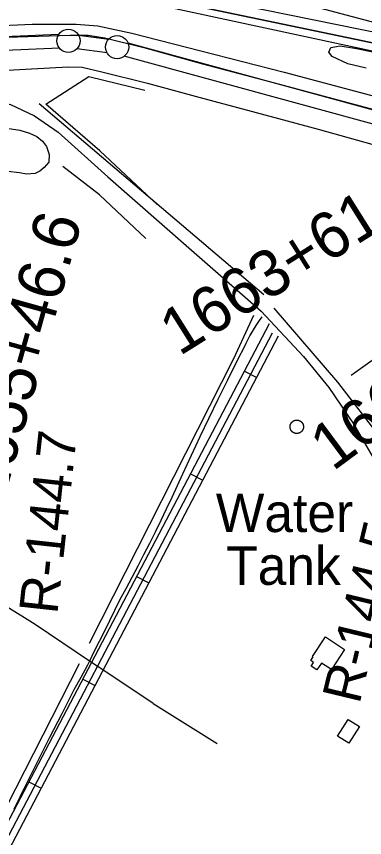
# Model space of a CAD drawing. Extents: x 3477039 to 3515015, y 546746 to 572297.
# Drawn here: x 3495798 to 3496548, y 561275 to 563045 of the extents above; entities that cross this region are included whole.
import ezdxf

# ---------------------------------------------------------------- set-up
doc = ezdxf.new("R2010")
doc.units = 0
for name, color, linetype in [('V-BLDG-OTLN', 7, 'Continuous'), ('V-DOMW-IDEN', 7, 'Continuous'), ('V-DOMW-TANK', 7, 'Continuous'), ('V-DTCH-CNTR', 7, 'Continuous'), ('V-FLOD-BASE', 7, 'Continuous'), ('V-LEVE-TOET', 7, 'Continuous'), ('V-RIVR-RANG-IDEN', 7, 'Continuous'), ('V-ROAD-CNTR', 7, 'Continuous'), ('V-RRAP-FSHR', 7, 'Continuous'), ('V-SITE-VEGE', 7, 'Continuous'), ('V-SURV-IDEN', 7, 'Continuous'), ('V-SURV-LINE', 7, 'Continuous'), ('V-TOPO-DPTH', 7, 'Continuous'), ('V-TOPO-MINR', 7, 'Continuous'), ('V-TOPO-SHOR', 7, 'Continuous')]:
    doc.layers.add(name, color=color, linetype=linetype)

msp = doc.modelspace()

# ---------------------------------------------------------------- linework, layer by layer
at = {"layer": 'V-BLDG-OTLN'}
for points in [[(3496463.4, 561707.2), (3496504.8, 561680.2), (3496476.7, 561637), (3496454.9, 561651.1), (3496445.3, 561636.4), (3496433, 561644.3), (3496438.2, 561652.3), (3496432.2, 561656.3), (3496437.3, 561664.2), (3496435.4, 561665.4)], [(3496512.8, 561529.5), (3496536.9, 561514.1), (3496513.9, 561478.2), (3496489.6, 561493.7)]]:
    msp.add_lwpolyline(points, close=True, dxfattribs=at)
at = {"layer": 'V-DOMW-TANK'}
for points in [[(3496387.7, 562163.5), (3496387.7, 562163.8), (3496387.8, 562164), (3496387.9, 562164.3), (3496387.9, 562164.5), (3496388, 562164.7), (3496388.1, 562165), (3496388.2, 562165.2), (3496388.2, 562165.5), (3496388.3, 562165.7), (3496388.4, 562165.9), (3496388.5, 562166.2), (3496388.6, 562166.4), (3496388.7, 562166.6), (3496388.8, 562166.9), (3496388.9, 562167.1), (3496389.1, 562167.3), (3496389.2, 562167.5), (3496389.3, 562167.7), (3496389.4, 562168), (3496389.6, 562168.2), (3496389.7, 562168.4), (3496389.8, 562168.6), (3496390, 562168.8), (3496390.1, 562169), (3496390.3, 562169.2), (3496390.4, 562169.4), (3496390.6, 562169.6), (3496390.8, 562169.8), (3496390.9, 562170), (3496391.1, 562170.2), (3496391.3, 562170.4), (3496391.4, 562170.6), (3496391.6, 562170.7), (3496391.8, 562170.9), (3496392, 562171.1), (3496392.2, 562171.3), (3496392.4, 562171.4), (3496392.6, 562171.6), (3496392.7, 562171.7), (3496392.9, 562171.9), (3496393.1, 562172.1), (3496393.3, 562172.2), (3496393.6, 562172.4), (3496393.8, 562172.5), (3496394, 562172.6), (3496394.2, 562172.8), (3496394.4, 562172.9), (3496394.6, 562173), (3496394.8, 562173.2), (3496395.1, 562173.3), (3496395.3, 562173.4), (3496395.5, 562173.5), (3496395.7, 562173.6), (3496396, 562173.7), (3496396.2, 562173.8), (3496396.4, 562173.9), (3496396.7, 562174), (3496396.9, 562174.1), (3496397.1, 562174.2), (3496397.4, 562174.3)], [(3496397.4, 562174.3), (3496397.6, 562174.3), (3496397.9, 562174.4), (3496398.1, 562174.5), (3496398.4, 562174.5), (3496398.6, 562174.6), (3496398.9, 562174.6), (3496399.1, 562174.7), (3496399.3, 562174.7), (3496399.6, 562174.8), (3496399.8, 562174.8), (3496400.1, 562174.8), (3496400.3, 562174.9), (3496400.6, 562174.9), (3496400.9, 562174.9), (3496401.1, 562174.9), (3496401.4, 562174.9), (3496401.6, 562174.9), (3496401.9, 562175), (3496402.1, 562174.9), (3496402.4, 562174.9), (3496402.6, 562174.9), (3496402.9, 562174.9), (3496403.1, 562174.9), (3496403.4, 562174.9), (3496403.6, 562174.8), (3496403.9, 562174.8), (3496404.1, 562174.8), (3496404.4, 562174.7), (3496404.6, 562174.7), (3496404.9, 562174.6), (3496405.1, 562174.6), (3496405.4, 562174.5), (3496405.6, 562174.4), (3496405.8, 562174.4), (3496406.1, 562174.3), (3496406.3, 562174.2), (3496406.6, 562174.2), (3496406.8, 562174.1), (3496407, 562174), (3496407.3, 562173.9), (3496407.5, 562173.8), (3496407.7, 562173.7), (3496408, 562173.6), (3496408.2, 562173.5), (3496408.4, 562173.4), (3496408.7, 562173.2), (3496408.9, 562173.1), (3496409.1, 562173), (3496409.3, 562172.9), (3496409.5, 562172.7), (3496409.7, 562172.6), (3496409.9, 562172.5), (3496410.2, 562172.3), (3496410.4, 562172.2), (3496410.6, 562172), (3496410.8, 562171.9), (3496411, 562171.7), (3496411.2, 562171.5), (3496411.3, 562171.4), (3496411.5, 562171.2), (3496411.7, 562171), (3496411.9, 562170.9), (3496412.1, 562170.7), (3496412.3, 562170.5), (3496412.4, 562170.3), (3496412.6, 562170.1), (3496412.8, 562169.9), (3496412.9, 562169.8), (3496413.1, 562169.6), (3496413.3, 562169.4), (3496413.4, 562169.2), (3496413.6, 562169), (3496413.7, 562168.7), (3496413.8, 562168.5), (3496414, 562168.3), (3496414.1, 562168.1), (3496414.2, 562167.9), (3496414.4, 562167.7), (3496414.5, 562167.5), (3496414.6, 562167.2), (3496414.7, 562167), (3496414.9, 562166.8), (3496415, 562166.6), (3496415.1, 562166.3), (3496415.2, 562166.1), (3496415.3, 562165.9), (3496415.4, 562165.6), (3496415.4, 562165.4), (3496415.5, 562165.2), (3496415.6, 562164.9), (3496415.7, 562164.7), (3496415.7, 562164.4), (3496415.8, 562164.2), (3496415.9, 562163.9), (3496415.9, 562163.7), (3496416, 562163.4), (3496416, 562163.2), (3496416.1, 562163), (3496416.1, 562162.7), (3496416.2, 562162.5)], [(3496401.3, 562146), (3496401, 562146), (3496400.8, 562146), (3496400.5, 562146.1), (3496400.3, 562146.1), (3496400, 562146.1), (3496399.8, 562146.1), (3496399.5, 562146.2), (3496399.3, 562146.2), (3496399, 562146.3), (3496398.8, 562146.3), (3496398.5, 562146.4), (3496398.3, 562146.4), (3496398, 562146.5), (3496397.8, 562146.6), (3496397.6, 562146.6), (3496397.3, 562146.7), (3496397.1, 562146.8), (3496396.8, 562146.9), (3496396.6, 562147), (3496396.4, 562147.1), (3496396.1, 562147.2), (3496395.9, 562147.3), (3496395.7, 562147.4), (3496395.4, 562147.5), (3496395.2, 562147.6), (3496395, 562147.7), (3496394.8, 562147.8), (3496394.6, 562148), (3496394.3, 562148.1), (3496394.1, 562148.2), (3496393.9, 562148.4), (3496393.7, 562148.5), (3496393.5, 562148.6), (3496393.3, 562148.8), (3496393.1, 562148.9), (3496392.9, 562149.1), (3496392.7, 562149.3), (3496392.5, 562149.4), (3496392.3, 562149.6), (3496392.1, 562149.7), (3496391.9, 562149.9), (3496391.7, 562150.1), (3496391.6, 562150.3), (3496391.4, 562150.5), (3496391.2, 562150.6), (3496391, 562150.8), (3496390.9, 562151), (3496390.7, 562151.2), (3496390.6, 562151.4), (3496390.4, 562151.6), (3496390.2, 562151.8), (3496390.1, 562152), (3496389.9, 562152.2), (3496389.8, 562152.4), (3496389.7, 562152.6), (3496389.5, 562152.8), (3496389.4, 562153.1), (3496389.3, 562153.3), (3496389.1, 562153.5), (3496389, 562153.7), (3496388.9, 562153.9), (3496388.8, 562154.2), (3496388.7, 562154.4), (3496388.6, 562154.6), (3496388.5, 562154.9), (3496388.4, 562155.1), (3496388.3, 562155.3), (3496388.2, 562155.6), (3496388.1, 562155.8), (3496388, 562156), (3496388, 562156.3), (3496387.9, 562156.5), (3496387.8, 562156.8), (3496387.8, 562157), (3496387.7, 562157.3), (3496387.7, 562157.5), (3496387.6, 562157.8), (3496387.6, 562158), (3496387.5, 562158.2), (3496387.5, 562158.5), (3496387.5, 562158.8), (3496387.4, 562159), (3496387.4, 562159.3), (3496387.4, 562159.5), (3496387.4, 562159.8), (3496387.4, 562160), (3496387.4, 562160.3), (3496387.4, 562160.5), (3496387.4, 562160.8), (3496387.4, 562161), (3496387.4, 562161.3), (3496387.4, 562161.5), (3496387.4, 562161.8), (3496387.4, 562162), (3496387.5, 562162.3), (3496387.5, 562162.5), (3496387.5, 562162.8), (3496387.6, 562163), (3496387.6, 562163.3), (3496387.7, 562163.5)], [(3496416.2, 562162.5), (3496416.2, 562162.2), (3496416.2, 562162), (3496416.2, 562161.7), (3496416.3, 562161.4), (3496416.3, 562161.2), (3496416.3, 562160.9), (3496416.3, 562160.7), (3496416.3, 562160.4), (3496416.3, 562160.2), (3496416.3, 562159.9), (3496416.3, 562159.7), (3496416.3, 562159.4), (3496416.2, 562159.2), (3496416.2, 562158.9), (3496416.2, 562158.7), (3496416.2, 562158.4), (3496416.1, 562158.2), (3496416.1, 562157.9), (3496416, 562157.7), (3496416, 562157.4), (3496415.9, 562157.2), (3496415.9, 562156.9), (3496415.8, 562156.7), (3496415.7, 562156.5), (3496415.7, 562156.2), (3496415.6, 562156), (3496415.5, 562155.7), (3496415.4, 562155.5), (3496415.3, 562155.3), (3496415.2, 562155), (3496415.1, 562154.8), (3496415, 562154.6), (3496414.9, 562154.3), (3496414.8, 562154.1), (3496414.7, 562153.9), (3496414.6, 562153.6), (3496414.5, 562153.4), (3496414.3, 562153.2), (3496414.2, 562153), (3496414.1, 562152.8), (3496413.9, 562152.6), (3496413.8, 562152.4), (3496413.7, 562152.1), (3496413.5, 562151.9), (3496413.4, 562151.7), (3496413.2, 562151.5), (3496413, 562151.3), (3496412.9, 562151.1), (3496412.7, 562151), (3496412.6, 562150.8), (3496412.4, 562150.6), (3496412.2, 562150.4), (3496412, 562150.2), (3496411.9, 562150), (3496411.7, 562149.9), (3496411.5, 562149.7), (3496411.3, 562149.5), (3496411.1, 562149.4), (3496410.9, 562149.2), (3496410.7, 562149), (3496410.5, 562148.9), (3496410.3, 562148.7), (3496410.1, 562148.6), (3496409.9, 562148.5), (3496409.7, 562148.3), (3496409.5, 562148.2), (3496409.2, 562148.1), (3496409, 562147.9), (3496408.8, 562147.8), (3496408.6, 562147.7), (3496408.4, 562147.6), (3496408.1, 562147.5), (3496407.9, 562147.3), (3496407.7, 562147.2), (3496407.4, 562147.1), (3496407.2, 562147), (3496407, 562147), (3496406.7, 562146.9), (3496406.5, 562146.8), (3496406.3, 562146.7), (3496406, 562146.6), (3496405.8, 562146.6), (3496405.5, 562146.5), (3496405.3, 562146.4), (3496405, 562146.4), (3496404.8, 562146.3), (3496404.5, 562146.3), (3496404.3, 562146.2), (3496404.1, 562146.2), (3496403.8, 562146.1), (3496403.6, 562146.1), (3496403.3, 562146.1), (3496403, 562146.1), (3496402.8, 562146), (3496402.5, 562146), (3496402.3, 562146), (3496402, 562146), (3496401.8, 562146), (3496401.5, 562146), (3496401.3, 562146)]]:
    msp.add_lwpolyline(points, dxfattribs=at)
at = {"layer": 'V-DTCH-CNTR'}
msp.add_line((3496092.7, 561563.5), (3496230.4, 561477.2), dxfattribs=at)
for points in [[(3496100.8, 562640), (3495977.7, 562755.4), (3495860.9, 562856.2), (3495953.6, 562916), (3496074.4, 562886.3)], [(3496076.7, 562566.7), (3495977, 562660.9), (3495897.5, 562721.4)], [(3496291.7, 562339), (3496296.1, 562347.7), (3496300.7, 562356.3), (3496305.6, 562364.8), (3496310.7, 562373.1), (3496316, 562381.3), (3496321.4, 562389.4), (3496327.1, 562397.3)], [(3496291.7, 562339), (3496271.5, 562299.2), (3496251.6, 562259.3), (3496231.9, 562219.3), (3496212.4, 562179.2), (3496193.1, 562138.9), (3496174.1, 562098.6), (3496155.3, 562058.1), (3496143.9, 562033), (3496132.4, 562008), (3496120.6, 561983.1), (3496108.7, 561958.2), (3496096.6, 561933.4), (3496084.3, 561908.8), (3496071.8, 561884.2), (3496059.1, 561859.7), (3496046.3, 561835.3), (3496033.2, 561811.1), (3496020, 561786.9)], [(3496092.7, 561563.5), (3495988.2, 561633.5), (3495955.5, 561655.2), (3495838.1, 561734.1), (3495714.9, 561810.1), (3495577.1, 561906.2), (3495498.3, 561961.4), (3495426.5, 562008.9)], [(3496020, 561786.9), (3496009.3, 561764.3), (3495998.3, 561741.9), (3495987.2, 561719.5), (3495975.9, 561697.3), (3495964.4, 561675.1)], [(3495964.4, 561675.1), (3495955.5, 561655.2), (3495950.9, 561646.6), (3495936.4, 561619.8), (3495921.6, 561593.1), (3495895.3, 561541.7), (3495869.1, 561490.2), (3495843.2, 561438.6), (3495817.5, 561386.9), (3495792, 561335.1)]]:
    msp.add_lwpolyline(points, dxfattribs=at)
at = {"layer": 'V-FLOD-BASE'}
for points in [[(3493763, 562937.8), (3493748.8, 562924.4), (3493748.8, 562915), (3493805.7, 562921.6), (3493844.5, 562926), (3493958.3, 562926.9), (3494101.5, 562930.6), (3494248.8, 562935.3), (3494380.3, 562942.6), (3494565.2, 562950.6), (3494744.2, 562959.8), (3494932, 562967.2), (3495077, 562972.6), (3495230.8, 562980.2), (3495398.1, 562986.6), (3495569.5, 562993.5), (3495730.9, 562998.8), (3495913.4, 563005), (3495952.1, 563004.7), (3495987.9, 562999.2), (3496072.2, 562978)], [(3496072.2, 562978), (3496198.7, 562942.9), (3496343.4, 562904.8), (3496508.7, 562860.1), (3496656.3, 562821), (3496768.6, 562788.9), (3496803.4, 562777.9), (3496844.1, 562761), (3496913.6, 562725.7), (3496965.5, 562693.5), (3496995.8, 562668.8), (3497043.2, 562621.4), (3497108.2, 562557.2), (3497182.4, 562484.5), (3497238.1, 562426.8), (3497262.9, 562394.2), (3497296.6, 562345.4), (3497348.1, 562259.2), (3497396.8, 562175.9), (3497451.3, 562085.2), (3497489.7, 562020.6), (3497518.9, 561971.4), (3497528.3, 561980.6)]]:
    msp.add_lwpolyline(points, dxfattribs=at)
at = {"layer": 'V-LEVE-TOET'}
for points in [[(3495687.3, 563022.5), (3495831.7, 563028.6), (3495926.2, 563028.9), (3495973, 563024.7), (3496046.4, 563009.4), (3496195.3, 562971.3), (3496374.8, 562924.8), (3496582.3, 562869.7), (3496703.2, 562835.8), (3496803.2, 562802.4), (3496872.1, 562770.5), (3496948, 562726.3), (3497018.1, 562674.3), (3497080.3, 562617.5), (3497178.2, 562522), (3497242.1, 562455.1), (3497293.3, 562393.5), (3497347.4, 562301.4), (3497421.9, 562175.4), (3497485.6, 562065.2), (3497528.4, 561986.7)], [(3494322.5, 562867.4), (3494552.6, 562873.3), (3494731, 562882.5), (3494949.4, 562892.1), (3495113.2, 562902), (3495289.3, 562911.8), (3495465.3, 562916.9), (3495609.7, 562922.9), (3495764.7, 562928.8), (3495909.1, 562936.5), (3495939.3, 562935.6), (3495982, 562925.8)], [(3495982, 562925.8), (3496080.3, 562901.6), (3496182.9, 562873.4), (3496314.4, 562838.5), (3496447.6, 562802.3), (3496648.4, 562746.4), (3496704.3, 562730.4), (3496741.9, 562716.1), (3496840.5, 562671.8), (3496902.4, 562636), (3496942.9, 562607.8), (3496974.2, 562579.6), (3497053.4, 562503), (3497129.1, 562433), (3497160.8, 562404), (3497181.7, 562382.8), (3497213, 562349), (3497226.9, 562325.3), (3497280.1, 562233.5), (3497366.8, 562092.6), (3497411.8, 562018), (3497436.5, 561975), (3497448.6, 561954.8)]]:
    msp.add_lwpolyline(points, dxfattribs=at)
at = {"layer": 'V-ROAD-CNTR'}
for p, q in [((3496289, 562280.4), (3496315.6, 562266.5)), ((3496172.9, 562059), (3496199.4, 562045.1)), ((3496056.7, 561837.7), (3496083.3, 561823.7)), ((3495940.6, 561616.3), (3495967.1, 561602.3)), ((3495824.4, 561394.9), (3495851, 561381))]:
    msp.add_line(p, q, dxfattribs=at)
for points in [[(3494343.6, 562821.8), (3494659.2, 562837.7), (3494960.8, 562850.6), (3495266.7, 562866.1), (3495500.8, 562876.5), (3495620.7, 562881), (3495682.1, 562878.7), (3495733.3, 562869.5), (3495784.9, 562855.1), (3495836.7, 562830.8), (3495887.9, 562796.1), (3495994.9, 562699.2), (3496169.5, 562546.5), (3496324.8, 562410.1), (3496416.3, 562312.2), (3496470.9, 562245.2), (3496524.2, 562166.7), (3496592.4, 562048.9), (3496710.4, 561850.3), (3496849.5, 561594.8), (3496885, 561531.7)], [(3495784.9, 562855.1), (3495836.7, 562830.8), (3495887.9, 562796.1), (3495994.9, 562699.2), (3496169.5, 562546.5), (3496324.8, 562410.1), (3496416.3, 562312.2), (3496470.9, 562245.2), (3496524.2, 562166.7), (3496592.4, 562048.9), (3496710.4, 561850.3), (3496849.5, 561594.8), (3496981.8, 561359.3), (3497177.7, 561015.5), (3497344.6, 560720.3), (3497526.1, 560393.2), (3497906.7, 559720.8)], [(3495568.8, 560907.9), (3496343.1, 562383.5)], [(3495582.1, 560900.9), (3496349.5, 562363.4)], [(3495595.4, 560894), (3496362.8, 562356.4)]]:
    msp.add_lwpolyline(points, dxfattribs=at)
at = {"layer": 'V-RRAP-FSHR'}
msp.add_lwpolyline([(3496209.8, 563128.7), (3496976.7, 562924.4), (3497518, 562705.6)], dxfattribs=at)
at = {"layer": 'V-SITE-VEGE'}
for points in [[(3496551.7, 562933.7), (3496511.6, 562942.8), (3496478.4, 562958.6), (3496470.6, 562968.5), (3496475.5, 562978.2), (3496495.2, 562982), (3496530.4, 562976), (3496565.6, 562968.9)], [(3495781.4, 562804), (3495804.9, 562800.3), (3495826, 562793.7), (3495841.8, 562786.5), (3495854.1, 562776.4), (3495862.8, 562765.2), (3495868, 562747.5), (3495867.3, 562731.1), (3495857.8, 562719.4), (3495848.3, 562711.8), (3495838.3, 562706.6), (3495819.4, 562705), (3495804.2, 562708), (3495778.9, 562710.6)]]:
    msp.add_lwpolyline(points, dxfattribs=at)
at = {"layer": 'V-SURV-LINE'}
for points in [[(3493765.8, 562915.6), (3495889.1, 563006.9)], [(3495931.5, 563005), (3495996.7, 562996.6)], [(3496037.9, 562988.4), (3496785, 562784.1)], [(3495890.4, 562976.9), (3493767.1, 562885.6)], [(3495992.9, 562966.9), (3495927.7, 562975.3)], [(3496777.1, 562755.2), (3496030, 562959.5)]]:
    msp.add_lwpolyline(points, dxfattribs=at)
for centre in [(3495909.8, 562992.7), (3496014.6, 562979.2)]:
    msp.add_circle(centre, 25, dxfattribs=at)
at = {"layer": 'V-TOPO-DPTH'}
msp.add_lwpolyline([(3498319.8, 562045.7), (3498313.5, 562051.2), (3498082.5, 562230.3), (3498076.1, 562235.1), (3498069.7, 562239.8), (3498063.1, 562244.4), (3498056.5, 562248.9), (3497671.4, 562503.8), (3497638.3, 562525.3), (3497605, 562546.6), (3497571.5, 562567.3), (3497537.7, 562587.8), (3497511.1, 562603.6), (3497490.4, 562615.8), (3497469.6, 562627.7), (3497448.6, 562639.4), (3496775, 562939.9), (3496760.2, 562945), (3496745.3, 562949.7), (3496730.3, 562953.9), (3495961.8, 563115.2)], dxfattribs=at)
at = {"layer": 'V-TOPO-MINR'}
for points in [[(3495964.3, 563134.9), (3496751.2, 562974.6), (3497473, 562657.7), (3497479.9, 562654), (3497486.7, 562650.2), (3497493.5, 562646.3), (3497589.2, 562589.5), (3497643.5, 562556.7), (3497697.4, 562523.3), (3497750.8, 562489), (3497803.8, 562454.2), (3498047.9, 562291.1)], [(3495961.8, 563115.2), (3496730.3, 562953.9), (3496745.3, 562949.7), (3496760.2, 562945), (3496775, 562939.9), (3497448.6, 562639.4), (3497469.6, 562627.7), (3497490.4, 562615.8), (3497511.1, 562603.6), (3497537.7, 562587.8), (3497571.5, 562567.3), (3497605, 562546.6), (3497638.3, 562525.3), (3497671.4, 562503.8), (3498056.5, 562248.9), (3498063.1, 562244.4), (3498069.7, 562239.8), (3498076.1, 562235.1), (3498082.5, 562230.3), (3498313.5, 562051.2), (3498319.8, 562045.7)], [(3496006.4, 563091.7), (3496748.2, 562931.5), (3496754.9, 562929.3), (3497413.8, 562612.3), (3497434.3, 562601.1), (3497454.8, 562589.7), (3497475.1, 562578.1), (3497495.3, 562566.3), (3497989.8, 562274.1)]]:
    msp.add_lwpolyline(points, dxfattribs=at)
at = {"layer": 'V-TOPO-SHOR'}
for p, q in [((3496330.9, 562444.8), (3495847, 562856.5)), ((3496518.7, 562271.5), (3496959.2, 562589.3)), ((3495558.1, 560913.7), (3495933.7, 561650.3))]:
    msp.add_line(p, q, dxfattribs=at)
for points in [[(3495955.3, 561693.7), (3496265.9, 562307.6), (3496309.2, 562401.5)], [(3496352.6, 562415.9), (3496489.8, 562257), (3496583.7, 562134.2), (3496887, 561578.1)]]:
    msp.add_lwpolyline(points, dxfattribs=at)

# ---------------------------------------------------------------- texts
at = {"layer": 'V-DOMW-IDEN'}
for s, p in [('Water', (3496227.3, 561933.5)), ('Tank', (3496249.9, 561819.6))]:
    msp.add_text(s, height=83, dxfattribs=at).set_placement(p)
at = {"layer": 'V-RIVR-RANG-IDEN'}
for s, rotation, p in [('R-144.7', 83.7935, (3495885.7, 561754.7)), ('R-144.5', 76.4561, (3496536.7, 561560.5))]:
    msp.add_text(s, height=83, rotation=rotation, dxfattribs=at).set_placement(p)
at = {"layer": 'V-SURV-IDEN'}
for s, rotation, p in [('1663+61.2', 32.1541, (3496148.8, 562311.7)), ('1655+46.6', 74.3683, (3495768.5, 561993.4)), ('1665+43.7', 36.5882, (3496479.6, 562063.2))]:
    msp.add_text(s, height=100, rotation=rotation, dxfattribs=at).set_placement(p)

doc.saveas('drawing.dxf')
